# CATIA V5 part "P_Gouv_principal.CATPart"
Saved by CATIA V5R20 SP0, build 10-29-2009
Part number: Gouv_principal
Bounding box of the stored display mesh (mm): x -46.645 to 46.645, y 107.791 to 390, z -1100 to 300
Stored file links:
  D:\Dropbox\MMS_GR3\bpantaleo\bpantaleo\bpantaleo\bpantaleo\P_Gouv_principal.CATPart
  D:\Dropbox\MMS_GR3\bpantaleo\bpantaleo\bpantaleo\bpantaleo\Gouvernail.CATProduct
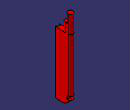
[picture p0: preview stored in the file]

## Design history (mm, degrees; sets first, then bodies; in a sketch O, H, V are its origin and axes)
External parameters (linked from other documents)
  External.Larg_Totale = 450 mm
  External.Long_Total = 1100 mm
Set1
  Point1 to Point8: linked copy from another document
  Point9 "Point.23": linked copy from another document
  Point10: linked copy from another document
Set2
  Plane1: type OffsetPt, RefPlane zx-plane, RefPoint Point7
  Plane2: type OffsetPt, RefPlane zx-plane, RefPoint Point6
  Plane3: type Offset, RefPlane xy-plane, Offset -275 {= -External.Long_Total /4}
Body1 (main body)
  Sketch1 "Esquisse_trans" on xy-plane, origin (0, 0, 0), H (1, 0, 0), V (0, 1, 0)
    axis line L1 (0, 493.2404) -> (0, -1.6829)
    arc A1 centre (0, 415) radius 35 from (-34.4998, 420.8959) to (34.4998, 420.8959) cw
    point P3 (0, 415)
    point P4 (-34.4998, 420.8959)
    point P5 (34.4998, 420.8959)
    reference projected point E1 (0, 450) from Point3
    arc A2 centre (-803.3534, 277.7108) radius 850 from (34.4998, 420.8959) to (0, 0) cw
    point P7 (34.4998, 420.8959)
    point P8 (0, 0)
    reference projected point E2 (0, 0) from Point2
    arc A3 centre (803.3534, 277.7108) radius 850 from (-34.4998, 420.8959) to (0, 0) ccw
    point P10 (-34.4998, 420.8959)
    point P11 (0, 0)
    reference projected point E3 (0, 0) from Point2
    radius A1 = 35 {= (35/450)*External.Larg_Totale}
    radius A2 = 850 {= (850/450)*External.Larg_Totale}
    radius A3 = 850 {= (850/450)*External.Larg_Totale}
    coincidence: L1 V, P3 L1, A1 E1, P8 E2, P7 P5, P10 P4, P11 E3, P8 P11
    tangency: A1 A2, A3 A1
  Sketch2 "Esquisse_long" on yz-plane, origin (0, 0, 0), H (0, 1, 0), V (0, 0, 1)
    line L1 (0, 0) -> (0, -1100)
    point P1 (0, -1100)
    line L2 (450, 0) -> (450, -948.2843)
    point P2 (450, 0)
    reference projected point E1 (450, -10) from Point3
    line L3 (450, 0) -> (0, 0)
    reference projected point E2 (0, -1100) from Point4
    line L4 (215.4416, -1100) -> (0, -1100)
    arc A1 centre (215.4416, -900) radius 200 from (356.8629, -1041.4214) to (215.4416, -1100) cw
    line L5 (450, -948.2843) -> (356.8629, -1041.4214)
    reference projected point E3 (360, -1010) from Point5
    radius A1 = 200 {= (200/450)*External.Larg_Totale}
    distance L5 E3 = 20
    angle L5 L4 = 45
    vertical: L1 V, L2 V
    coincidence: P2 H, L2 E1, P1 E2
    horizontal: L3 H
    perpendicularity: L4 L2, L4 L1
    tangency: A1 L4, L5 A1
  SolidCombine1: FirstComponentProfile Sketch1, FirstComponentDirection Sketch1, SecondComponentProfile Sketch2, SecondComponentDirection Sketch2
  Sketch3 on xy-plane, origin (0, 0, 0), H (1, 0, 0), V (0, 1, 0)
    axis line L1 (0, 575.6469) -> (0, -71.3955)
    construction arc A1 centre (0, 415) radius 35 from (-34.4998, 420.8959) to (34.4998, 420.8959) cw
    point P3 (0, 415)
    point P5 (34.4998, 420.8959)
    reference projected point E1 (0, 450) from Point3
    construction arc A2 centre (-803.3534, 277.7108) radius 850 from (34.4998, 420.8959) to (0, 0) cw
    point P7 (34.4998, 420.8959)
    point P8 (0, 0)
    construction arc A3 centre (803.3534, 277.7108) radius 850 from (-34.4998, 420.8959) to (0, 0) ccw
    point P10 (0, 0)
    reference projected point E2 (0, 0) from Point2
    reference projected point E3 (0, 0) from Point2
    point P11 (-30.9581, 115.1552)
    point P12 (30.9581, 115.1552)
    arc A4 centre (-803.3534, 277.7108) radius 850 from (30.9581, 115.1552) to (0, 0) cw
    arc A5 centre (803.3534, 277.7108) radius 850 from (-30.9581, 115.1552) to (0, 0) ccw
    point P15 (0, 0)
    arc A6 centre (0, 111.5613) radius 31.166 from (30.9581, 115.1552) to (-30.9581, 115.1552) ccw
    point P16 (0, 111.5613)
    point P17 (0, 142.7273)
    reference projected point E4 (0, 142.7273) from Point10
    radius A1 = 35 {= (35/450)*External.Larg_Totale}
    radius A2 = 850 {= (850/450)*External.Larg_Totale}
    radius A3 = 850 {= (850/450)*External.Larg_Totale}
    vertical: L1 V
    coincidence: L1 V, P3 L1, A1 E1, P7 A1, P8 E2, P7 P5, P10 E3, P11 A3, P12 A2, P15 A2, P15 L1, A4 A2, A5 A3, O P15, A6 P17, P17 L1, P16 L1, A6 E4
    tangency: A2 A1, A3 A1
  Pocket1 "Poche_ar": profile Sketch3, direction (0, 0, -1), length 1100 {= External.Long_Total}
  Sketch4 on xy-plane, origin (0, 0, 0), H (1, 0, 0), V (0, 1, 0)
    axis line L1 (0, 510.3028) -> (0, -197.5919)
    construction arc A1 centre (0, 415) radius 35 from (-34.4998, 420.8959) to (34.4998, 420.8959) cw
    point P3 (0, 415)
    point P4 (-34.4998, 420.8959)
    point P5 (34.4998, 420.8959)
    reference projected point E1 (0, 450) from Point3
    construction arc A2 centre (-803.3534, 277.7108) radius 850 from (34.4998, 420.8959) to (0, 0) cw
    construction arc A3 centre (803.3534, 277.7108) radius 850 from (-34.4998, 420.8959) to (0, 0) ccw
    arc A4 centre (0, 346.2739) radius 43.7261 from (43.5677, 349.9922) to (-43.5677, 349.9922) ccw
    point P8 (0, 346.2739)
    point P9 (43.5677, 349.9922)
    point P10 (-43.5677, 349.9922)
    reference projected point E2 (0, 390) from Point7
    arc A5 centre (0, 415) radius 35 from (-34.4998, 420.8959) to (34.4998, 420.8959) cw
    point P12 (-34.4998, 420.8959)
    point P13 (34.4998, 420.8959)
    arc A6 centre (-803.3534, 277.7108) radius 850 from (34.4998, 420.8959) to (43.5677, 349.9922) cw
    point P15 (43.5677, 349.9922)
    arc A7 centre (803.3534, 277.7108) radius 850 from (-34.4998, 420.8959) to (-43.5677, 349.9922) ccw
    point P17 (-34.4998, 420.8959)
    point P18 (-43.5677, 349.9922)
    radius A1 = 35 {= (35/450)*External.Larg_Totale}
    radius A2 = 850 {= (850/450)*External.Larg_Totale}
    radius A3 = 850 {= (850/450)*External.Larg_Totale}
    coincidence: L1 V, P3 L1, A1 E1, P8 L1, P9 A2, P10 A3, A4 E2, P13 A2, P12 A3, A5 A1, P15 A4, P15 A2, A6 A2, P17 P4, P18 P10, A7 A3, P5 P13, P9 P15
    tangency: A2 A1, A3 A1, A4 A7
  Pocket2 "Poche_av": profile Sketch4, direction (0, 0, -1), length 1100 {= External.Long_Total}
  Sketch5 on Plane1, origin (0, 390, 0), H (-1, 0, 0), V (0, 0, 1)
    line L1 (-100, -1010) -> (100, -1010)
    point P1 (-100, -1010)
    reference projected point E1 (0, -1010) from Point5
    line L2 (-100, -950) -> (100, -950)
    line L3 (100, -950) -> (100, -1010)
    line L4 (-100, -950) -> (-100, -1010)
    point P5 (-100, -1010)
    reference projected point E2 (0, -1010) from Point5
    length L3 = 60
    length L2 = 200 {= (200/450)*External.Larg_Totale}
    distance E2 L4 = 100 {= Sketch5.length(L2)/2}
    horizontal: L1 H, L2 H
    coincidence: L1 E1, P5 L1, P5 P1
    perpendicularity: L3 L2, L3 L1, L4 L1
  Pocket3 "Poche_liaison_Gouv/vol_ar": profile Sketch5, direction (0, -1, 0), length 60 {= (60/450)*External.Larg_Totale}
  Sketch6 on Plane2, origin (0, 152.7273, 0), H (-1, 0, 0), V (0, 0, 1)
    circle A1 centre (0, -275) radius 12
    point P1 (0, -275)
    distance P1 H = 275 {= External.Long_Total /4}
    radius A1 = 12
    coincidence: P1 V
  Pad1 "Extrusion_charniere_1": profile Sketch6, direction (0, -1, 0), length 30 {= (30/450)*External.Larg_Totale}
  Sketch7 on Plane3, origin (0, 0, -275), H (1, 0, 0), V (0, 1, 0)
    circle A1 centre (0, 122.7273) radius 15
    point P1 (0, 122.7273)
    reference projected point E1 (0, 122.7273) from Point8
    radius A1 = 15
    coincidence: P1 E1
  Pad2 "Extrusion_charniere_2": profile Sketch7, direction (0, 0, 1), length 30, opposite side length 20
  Sketch8 on Plane3, origin (0, 0, -275), H (1, 0, 0), V (0, 1, 0)
    circle A1 centre (0, 122.7273) radius 8
    point P1 (0, 122.7273)
    reference projected point E1 (0, 122.7273) from Point8
    radius A1 = 8
    coincidence: P1 E1
  Pad3 "Extrusion_charniere_3": profile Sketch8, direction (0, 0, 1), length 55
  Fillet1 "Congé_charniere": radius 3, on face of Pad2 from Sketch7.A1; face of Pad1 from Sketch6.A1; face of Pad3 from Sketch8.A1
  RectPattern1: of Pad1, Sketch6, Pad2, Sketch7, Pad3, Sketch8, Fillet1, direction 1 instances 3, spacing 275 {= External.Long_Total /4}, along Z axis reversed
  Sketch9 on face of Pocket3 from Sketch5.L1, origin (25.2915, 364.9711, -1010), H (1, 0, 0), V (0, 1, 0)
    point P1 (-25.2915, -4.9711)
    reference projected point E1 (-25.2915, -4.9711) from Point5
    coincidence: P1 E1
  Hole1: placed by Sketch9, at (0, 360, -1010) direction (0, 0, -1), diameter 10, depth 20
  Sketch10 on xy-plane, origin (0, 0, 0), H (1, 0, 0), V (0, 1, 0)
    line L1 (-75, 400) -> (75, 400)
    line L2 (75, 400) -> (75, 0)
    line L3 (75, 0) -> (-75, 0)
    line L4 (-75, 0) -> (-75, 400)
    length L2 = 400 {= (400/450)*External.Larg_Totale}
    length L1 = 150 {= (150/450)*External.Larg_Totale}
    distance L4 V = 75 {= Sketch10.length(L1) /2}
    horizontal: L1 H, L3 H
    vertical: L2 V, L4 V
    coincidence: L3 H
  Pocket4 "Poche_10mm": profile Sketch10, direction (0, 0, -1), length 10
  Sketch11 on xy-plane, origin (0, 0, 0), H (1, 0, 0), V (0, 1, 0)
    axis line L1 (0, 507.0217) -> (0, -151.7792)
    construction arc A1 centre (0, 415) radius 35 from (-34.4998, 420.8959) to (34.4998, 420.8959) cw
    point P3 (0, 415)
    reference projected point E1 (0, 450) from Point3
    construction arc A2 centre (-803.3534, 277.7108) radius 850 from (34.4998, 420.8959) to (0, 0) cw
    construction arc A3 centre (803.3534, 277.7108) radius 850 from (-34.4998, 420.8959) to (0, 0) ccw
    circle A4 centre (0, 346.2739) radius 43.7261
    point P8 (0, 346.2739)
    reference projected point E2 (0, 390) from Point7
    radius A1 = 35 {= (35/450)*External.Larg_Totale}
    radius A2 = 850 {= (850/450)*External.Larg_Totale}
    radius A3 = 850 {= (850/450)*External.Larg_Totale}
    coincidence: L1 V, P3 L1, A1 E1, P8 L1, A4 E2
    tangency: A2 A1, A3 A1, A4 A2
  Pad4 "Extrusion_axe_gouv_coque": profile Sketch11, direction (0, 0, 1), length 300, opposite side length 10
  Sketch12 on xy-plane, origin (0, 0, 0), H (1, 0, 0), V (0, 1, 0)
    axis line L1 (0, 529.2251) -> (0, -17.6115)
    construction arc A1 centre (0, 415) radius 35 from (-34.4998, 420.8959) to (34.4998, 420.8959) cw
    point P3 (0, 415)
    reference projected point E1 (0, 450) from Point3
    construction arc A2 centre (-803.3534, 277.7108) radius 850 from (34.4998, 420.8959) to (0, 0) cw
    construction arc A3 centre (803.3534, 277.7108) radius 850 from (-34.4998, 420.8959) to (0, 0) ccw
    arc A4 centre (0, 346.2739) radius 43.7261 from (43.5677, 349.9922) to (-43.5677, 349.9922) ccw
    point P8 (0, 346.2739)
    point P9 (43.5677, 349.9922)
    point P10 (-43.5677, 349.9922)
    reference projected point E2 (0, 390) from Point7
    arc A5 centre (-803.3534, 277.7108) radius 850 from (43.5677, 349.9922) to (46.3521, 300.0843) cw
    arc A6 centre (803.3534, 277.7108) radius 850 from (-43.5677, 349.9922) to (-46.3521, 300.0843) ccw
    arc A7 centre (0, 298.8638) radius 46.3682 from (46.3521, 300.0843) to (-46.3521, 300.0843) cw
    point P15 (0, 298.8638)
    point P16 (0, 252.4956)
    reference projected point E3 (0, 298.8638) from Point9
    radius A3 = 850 {= (850/450)*External.Larg_Totale}
    radius A2 = 850 {= (850/450)*External.Larg_Totale}
    radius A1 = 35 {= (35/450)*External.Larg_Totale}
    vertical: L1 V
    coincidence: L1 V, A1 E1, P3 L1, P8 L1, A4 E2, P9 A2, P10 A3, A5 A2, A6 A3, A7 P16, P16 L1, E3 P15
    tangency: A2 A1, A3 A1, A4 A5, A5 A7
  Pad5 "Extrusion_frette": profile Sketch12, direction (0, 0, 1), length 150, opposite side length 10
